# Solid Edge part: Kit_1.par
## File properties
Sűrűség: 0,000 kg/m^3
Pontosság: 0,990
Author: bmolnar
Last saved by: bmolnar
Revision: 77
Username: bmolnar
Dokumentum tartalom típus: 0
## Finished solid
Body 1: solid body, 23 faces, 29 edges, 25 vertices, 2 separate solids.
  Faces by surface: plane 8, cone 7, cylinder 6, torus 2
  Edges by curve: circle 21, line 8
Bounding box of the edges (mm; curved faces can reach further): 19.000 x 18.450 x 3.100, from (-9.5, -9.5, 43.6) to (9.5, 8.95, 46.7).
Cylindrical faces by radius (mm): R4.21 x1, R4.6 x1, R6.6 x1, R8.5 x1, R8.95 x1, R9.5 x1
Conical faces (half-angle, radius in mm at the cone's reference point): 14 deg R4.105 x1, 14 deg R4.3042 x1, 17 deg R4.105 x1, 42.5 deg R4.0959 x1, 45 deg R4.75 x1, 45 deg R6.45 x1, 87 deg R4.0979 x1
Toroidal faces (ring radius, tube radius in mm): R4.5656 r0.1575 x1, R7 r0.4 x1
Planar faces by outward normal: +z 4, -z 2, oblique 2
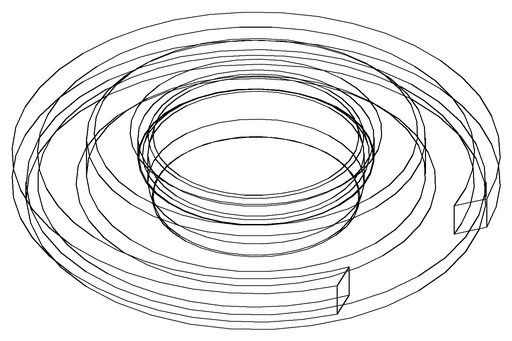
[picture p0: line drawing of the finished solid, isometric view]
